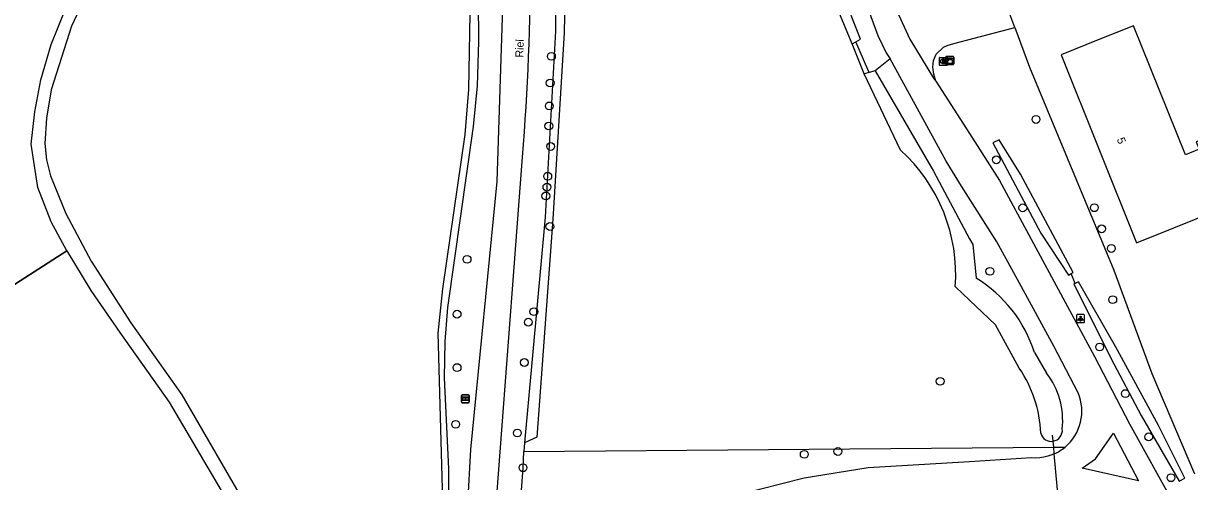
# Model space of a CAD drawing. Extents: x 163863 to 164644, y 379566 to 382155.
# Drawn here: x 164381.7 to 164527.5, y 381338.5 to 381395.8 of the extents above; entities that cross this region are included whole.
import ezdxf

# ---------------------------------------------------------------- set-up
doc = ezdxf.new("R2010")
doc.units = 0
for name, color, linetype in [('IMGEO_Boom', 7, 'Continuous'), ('IMGEO_Bouwland', 7, 'Continuous'), ('IMGEO_Duiker', 7, 'Continuous'), ('IMGEO_Groenvoorziening', 7, 'Continuous'), ('IMGEO_Hek', 7, 'Continuous'), ('IMGEO_Informatiebord', 7, 'Continuous'), ('IMGEO_Kast', 7, 'Continuous'), ('IMGEO_Lichtpunt', 7, 'Continuous'), ('IMGEO_Openbare_ruimte_label', 7, 'Continuous'), ('IMGEO_Pand', 7, 'Continuous'), ('IMGEO_Pand_nummerreeks', 7, 'Continuous'), ('IMGEO_Rijbaan_lokaal_gesloten', 7, 'Continuous'), ('IMGEO_Rijbaan_lokaal_onverhard', 7, 'Continuous'), ('IMGEO_Rioolput', 7, 'Continuous'), ('IMGEO_Waterloop', 7, 'Continuous')]:
    doc.layers.add(name, color=color, linetype=linetype)

msp = doc.modelspace()

# ---------------------------------------------------------------- linework, layer by layer
at = {"layer": 'IMGEO_Boom'}
for centre in [(164447.74, 381391.69), (164447.58, 381388.35), (164447.48, 381385.49), (164508.3, 381383.8), (164447.41, 381382.97), (164447.64, 381380.42), (164503.34, 381378.75), (164447.28, 381376.69), (164447.18, 381375.33), (164447.05, 381374.23), (164506.65, 381372.74), (164515.59, 381372.75), (164447.55, 381370.4), (164516.5, 381370.12), (164517.72, 381367.66), (164437.2, 381366.29), (164502.54, 381364.8), (164517.89, 381361.25), (164435.95, 381359.43), (164445.55, 381359.75), (164444.85, 381358.43), (164516.26, 381355.32), (164444.35, 381353.39), (164435.95, 381352.75), (164496.32, 381351.04), (164519.46, 381349.5), (164435.78, 381345.66), (164443.48, 381344.56), (164522.39, 381344.08), (164479.34, 381341.9), (164483.54, 381342.26), (164444.19, 381340.22), (164525.17, 381338.97)]:
    msp.add_circle(centre, 0.489, dxfattribs=at)
at = {"layer": 'IMGEO_Bouwland'}
msp.add_lwpolyline([(164287.52, 381296.47), (164317.88, 381319.5), (164350.6, 381343.85), (164387.17, 381367.35)], dxfattribs=at)
at = {"layer": 'IMGEO_Duiker'}
for points in [[(164487.45, 381389.67), (164487.29, 381390.03), (164485.77, 381393.51)], [(164513.19, 381363.29), (164512.71, 381364.51)], [(164511.24, 381334.6), (164511.23, 381334.72), (164510.95, 381337.93), (164510.59, 381341.96), (164510.51, 381342.79), (164510.45, 381343.54), (164510.38, 381344.3)]]:
    msp.add_lwpolyline(points, dxfattribs=at)
at = {"layer": 'IMGEO_Groenvoorziening'}
for points in [[(164505.66, 381395.29), (164507.47, 381390.32), (164518.04, 381364.93), (164522.77, 381352.02), (164528.1, 381339.46)], [(164486.82, 381389.49), (164485.33, 381393.26)], [(164490.06, 381391.38), (164488.22, 381389.88)], [(164444.37, 381343.32), (164444.31, 381342.24)], [(164443.5, 381329.17), (164443.79, 381334.56), (164444.19, 381340.22), (164444.31, 381342.24)], [(164444.31, 381342.24), (164510.51, 381342.79), (164511.93, 381342.81)]]:
    msp.add_lwpolyline(points, dxfattribs=at)
at = {"layer": 'IMGEO_Hek'}
msp.add_lwpolyline([(164387.17, 381367.35), (164350.6, 381343.85), (164317.88, 381319.5), (164287.52, 381296.47), (164311.91, 381267.33)], dxfattribs=at)
at = {"layer": 'IMGEO_Informatiebord'}
for p, q in [((164436.49, 381348.45), (164436.49, 381349.25)), ((164436.49, 381349.25), (164436.49, 381348.45)), ((164436.59, 381349.35), (164437.38, 381349.35)), ((164437.38, 381349.35), (164436.59, 381349.35)), ((164437.48, 381349.25), (164437.48, 381348.45)), ((164437.48, 381348.45), (164437.48, 381349.25)), ((164437.38, 381348.35), (164436.59, 381348.35)), ((164436.59, 381348.35), (164437.38, 381348.35))]:
    msp.add_line(p, q, dxfattribs=at)
for points in [[(164436.6, 381349.08), (164437.38, 381349.08), (164437.38, 381348.62), (164436.6, 381348.62), (164436.6, 381349.08)], [(164436.66, 381349.02), (164436.66, 381348.68), (164436.94, 381348.68), (164436.94, 381348.9), (164437.04, 381348.9), (164437.04, 381348.68), (164437.32, 381348.68), (164437.32, 381349.02), (164437.04, 381349.02), (164437.04, 381348.94), (164436.94, 381348.94), (164436.94, 381349.02), (164436.66, 381349.02)]]:
    msp.add_lwpolyline(points, dxfattribs=at)
for centre, start, end in [((164436.59, 381349.25), 90, 180), ((164436.59, 381349.25), 90, 180), ((164437.38, 381349.25), 0, 90), ((164437.38, 381349.25), 360, 90), ((164436.59, 381348.45), 180, 270), ((164436.59, 381348.45), 180, 270), ((164437.38, 381348.45), 270, 0), ((164437.38, 381348.45), 270, 0)]:
    msp.add_arc(centre, 0.1, start, end, dxfattribs=at)
at = {"layer": 'IMGEO_Kast'}
for p, q in [((164497.02, 381390.76), (164497.02, 381391.6)), ((164497.02, 381391.6), (164497.02, 381390.76)), ((164497.1, 381391.68), (164497.94, 381391.68)), ((164497.94, 381391.68), (164497.1, 381391.68)), ((164498.02, 381391.61), (164498.02, 381390.77)), ((164498.02, 381390.77), (164498.02, 381391.61)), ((164497.95, 381390.68), (164497.11, 381390.68)), ((164497.11, 381390.68), (164497.95, 381390.68))]:
    msp.add_line(p, q, dxfattribs=at)
for points in [[(164497.22, 381391.47), (164497.82, 381391.47), (164497.82, 381391.39), (164497.22, 381391.39), (164497.22, 381391.47)], [(164497.22, 381391.3), (164497.82, 381391.3), (164497.82, 381390.81), (164497.22, 381390.81), (164497.22, 381391.3)]]:
    msp.add_lwpolyline(points, dxfattribs=at)
msp.add_circle((164497.3, 381391.14), 0.0377, dxfattribs=at)
for centre, start, end in [((164497.1, 381391.6), 92.4484, 184.2845), ((164497.1, 381391.6), 92.4484, 184.2845), ((164497.94, 381391.6), 2.4484, 94.2845), ((164497.94, 381391.6), 2.4484, 94.2845), ((164497.1, 381390.76), 182.4484, 274.2845), ((164497.1, 381390.76), 182.4484, 274.2845), ((164497.94, 381390.76), 272.4484, 4.2845), ((164497.94, 381390.76), 272.4484, 4.2845)]:
    msp.add_arc(centre, 0.0779, start, end, dxfattribs=at)
at = {"layer": 'IMGEO_Lichtpunt'}
for p, q in [((164513.37, 381359.29), (164513.37, 381358.48)), ((164513.37, 381359.29), (164513.37, 381358.48)), ((164514.27, 381359.39), (164513.46, 381359.39)), ((164514.27, 381359.39), (164513.46, 381359.39)), ((164514.36, 381358.48), (164514.36, 381359.29)), ((164514.36, 381358.48), (164514.36, 381359.29)), ((164513.46, 381358.39), (164514.27, 381358.39)), ((164513.46, 381358.39), (164514.27, 381358.39))]:
    msp.add_line(p, q, dxfattribs=at)
for points in [[(164513.74, 381358.95), (164513.78, 381358.93), (164513.59, 381358.66), (164513.55, 381358.69), (164513.74, 381358.95)], [(164513.84, 381358.91), (164513.89, 381358.91), (164513.89, 381358.58), (164513.84, 381358.58), (164513.84, 381358.91)], [(164513.95, 381358.93), (164513.99, 381358.95), (164514.18, 381358.69), (164514.14, 381358.66), (164513.95, 381358.93)]]:
    msp.add_lwpolyline(points, dxfattribs=at)
msp.add_circle((164513.87, 381359.09), 0.0994, dxfattribs=at)
for centre, start, end in [((164513.46, 381359.29), 90, 180), ((164513.46, 381359.29), 90, 180), ((164514.27, 381359.29), 0, 90), ((164514.27, 381359.29), 0, 90), ((164513.46, 381358.48), 180, 270), ((164513.46, 381358.48), 180, 270), ((164514.27, 381358.48), 270, 0), ((164514.27, 381358.48), 270, 360)]:
    msp.add_arc(centre, 0.0946, start, end, dxfattribs=at)
at = {"layer": 'IMGEO_Pand'}
msp.add_lwpolyline([(164520.5, 381395.51), (164516.07, 381393.74), (164511.43, 381391.87), (164520.86, 381368.36), (164525.51, 381370.22), (164530.92, 381372.39), (164530.81, 381372.66), (164531.54, 381372.95), (164531.69, 381372.56), (164535.63, 381374.14), (164532.25, 381382.56), (164528.32, 381380.98), (164528.68, 381380.07), (164526.97, 381379.39), (164520.5, 381395.51)], dxfattribs=at)
at = {"layer": 'IMGEO_Rijbaan_lokaal_gesloten'}
for points in [[(164442.22, 381457.68), (164442.24, 381448.35), (164442.26, 381444.54), (164442.31, 381432.69), (164442.03, 381410.67), (164440.93, 381376.03), (164437.62, 381342.51), (164436.86, 381328.83), (164436.27, 381323.37), (164435.38, 381319.58), (164433.55, 381313.72), (164431.24, 381307.56), (164428.74, 381302.37)], [(164440.65, 381333.45), (164440.75, 381334.49), (164441.34, 381342.21), (164444.13, 381379.08)]]:
    msp.add_lwpolyline(points, dxfattribs=at)
msp.add_arc((164127.19, 381404.33), 317.95, 355.4455, 359.9916, dxfattribs=at)
at = {"layer": 'IMGEO_Rijbaan_lokaal_onverhard'}
for points in [[(164453.83, 381458.42), (164461.3, 381450.96), (164468.06, 381442.36), (164472.89, 381433.3), (164481.62, 381413.16), (164488.52, 381394.29), (164489.58, 381392.13), (164490.06, 381391.38)], [(164489.95, 381399.53), (164492.54, 381393.86), (164495.51, 381388.98), (164495.77, 381388.57)], [(164505.66, 381395.29), (164504.8, 381397.62)], [(164495.77, 381388.57), (164495.53, 381389.45), (164495.39, 381390.32), (164495.47, 381391.17), (164495.84, 381391.97), (164496.74, 381392.84), (164497.2, 381393.06), (164498.04, 381393.32), (164505.66, 381395.29)], [(164513.55, 381349.6), (164510.53, 381355.42), (164506.25, 381363.3), (164503.41, 381368.49), (164499.01, 381375.46), (164497.08, 381378.56), (164490.06, 381391.38)], [(164495.77, 381388.57), (164500, 381382.04), (164503.75, 381376.16), (164515.61, 381354.14), (164519.97, 381345.71), (164525.51, 381335.7), (164527.86, 381330.74), (164529.04, 381328.58), (164531.51, 381322.61), (164532.72, 381318.95), (164540.2, 381293.84), (164541.11, 381291.26), (164542, 381286.69), (164542.93, 381279.72), (164544.02, 381275.23)], [(164517.97, 381344.54), (164521.12, 381338.58), (164514.08, 381340.16), (164515.72, 381341.34), (164517.97, 381344.54)], [(164510.59, 381341.96), (164510.3, 381341.84), (164509.8, 381341.67), (164509.29, 381341.54), (164508.78, 381341.47), (164508.25, 381341.43), (164507.73, 381341.45), (164500, 381340.97), (164487.33, 381340.19), (164479.32, 381338.91), (164471.46, 381336.92), (164464.88, 381334.66), (164449.43, 381328.52), (164449.13, 381328.41), (164448.56, 381328.25), (164447.99, 381328.15), (164447.4, 381328.1), (164446.81, 381328.1), (164446.23, 381328.15), (164445.65, 381328.25), (164445.09, 381328.41), (164444.54, 381328.61), (164444.01, 381328.87), (164443.5, 381329.17)]]:
    msp.add_lwpolyline(points, dxfattribs=at)
for centre, radius, start, end in [((164508.17, 381347.29), 5.86, 310.0111, 23.194), ((164508.16, 381347.3), 5.87, 294.4431, 310.0184)]:
    msp.add_arc(centre, radius, start, end, dxfattribs=at)
at = {"layer": 'IMGEO_Rioolput'}
for p, q in [((164496.23, 381390.64), (164496.23, 381391.49)), ((164496.3, 381391.56), (164497.16, 381391.56)), ((164497.23, 381391.49), (164497.23, 381390.64)), ((164497.16, 381390.56), (164496.3, 381390.56)), ((164496.74, 381390.78), (164496.71, 381390.78)), ((164496.72, 381391.34), (164496.74, 381391.34))]:
    msp.add_line(p, q, dxfattribs=at)
for points in [[(164496.23, 381390.64), (164496.23, 381391.49)], [(164496.3, 381391.56), (164497.16, 381391.56)], [(164497.23, 381391.49), (164497.23, 381390.64)], [(164497.16, 381390.56), (164496.3, 381390.56)], [(164496.82, 381391.26), (164496.56, 381391.26), (164496.56, 381390.86)], [(164496.56, 381390.86), (164496.69, 381390.86), (164496.69, 381391.02), (164496.7, 381391.02)], [(164496.74, 381391.18), (164496.69, 381391.18), (164496.69, 381391.1)], [(164496.69, 381391.1), (164496.74, 381391.1)], [(164496.75, 381390.99), (164496.82, 381390.86), (164496.96, 381390.86), (164496.89, 381390.99)]]:
    msp.add_lwpolyline(points, dxfattribs=at)
for centre, radius, start, end in [((164496.3, 381391.49), 0.0765, 91.552, 178.448), ((164496.3, 381391.49), 0.0765, 91.552, 178.448), ((164497.15, 381391.49), 0.0765, 1.552, 88.448), ((164497.15, 381391.49), 0.0765, 1.552, 88.448), ((164496.3, 381390.64), 0.0765, 181.552, 268.448), ((164496.3, 381390.64), 0.0765, 181.552, 268.448), ((164496.7, 381390.97), 0.0533, 26.0293, 88.6989), ((164496.75, 381391.08), 0.0964, 77.0061, 93.1865), ((164496.73, 381391.29), 0.19, 274.7715, 282.9687), ((164496.76, 381391.14), 0.0378, 276.6634, 79.6772), ((164496.82, 381391.15), 0.109, 350.3612, 89.416), ((164496.81, 381391.15), 0.112, 277.5842, 350.9817), ((164496.8, 381390.93), 0.108, 29.5134, 73.7905), ((164497.15, 381390.64), 0.0765, 271.552, 358.448), ((164497.15, 381390.64), 0.0765, 271.552, 358.448)]:
    msp.add_arc(centre, radius, start, end, dxfattribs=at)
for centre, major_axis, ratio, start_param, end_param in [((164496.72, 381391.06), (-0.387, 0.002), 0.722429, 4.712389, 7.853982), ((164496.74, 381391.06), (-0.39, 0.002), 0.717154, 1.570796, 4.712389)]:
    msp.add_ellipse(centre, major_axis=major_axis, ratio=ratio, start_param=start_param, end_param=end_param, dxfattribs=at)
at = {"layer": 'IMGEO_Waterloop'}
for points in [[(164448.54, 381452.5), (164447.88, 381447.15), (164447.94, 381444.47), (164448.45, 381420.11), (164448.25, 381394.83), (164446.95, 381371.56), (164444.37, 381343.32)], [(164449.93, 381450.68), (164449.82, 381420.02), (164449.32, 381394.65), (164447.9, 381371.31), (164445.92, 381344.04), (164444.37, 381343.32)], [(164423.74, 381298.57), (164430.45, 381312.12), (164432.38, 381317.5), (164434.01, 381324.36), (164434.72, 381330), (164434.91, 381333.02), (164434.92, 381340.08), (164434.38, 381351.46), (164434.48, 381356.02), (164434.81, 381360.28), (164438.01, 381382.93), (164438.49, 381387.99), (164438.66, 381393.57), (164438.58, 381403.85), (164438.23, 381407.47), (164437.47, 381412.38), (164437.16, 381415.96), (164437.21, 381424.46), (164437.58, 381427.9), (164436.26, 381427.88)], [(164434.19, 381336.08), (164433.57, 381357.04), (164434.19, 381362.6), (164436.96, 381381.93), (164437.41, 381387.54), (164437.63, 381399.41), (164436.95, 381408.32), (164436.41, 381411.28), (164435.98, 381417.22), (164436.15, 381420.7), (164436.03, 381423.26), (164436.26, 381427.88)], [(164485.33, 381393.26), (164477.93, 381411.1), (164472.47, 381424.73)], [(164485.33, 381393.26), (164485.77, 381393.51), (164486.37, 381393.84), (164483.6, 381400.91), (164479.59, 381410.3), (164479.27, 381411.35)], [(164387.17, 381367.35), (164385.24, 381370.99), (164383.54, 381375.27), (164382.71, 381380.71), (164383.19, 381384.77), (164383.93, 381388.75), (164385.23, 381393.19), (164386.96, 381397.52), (164389.07, 381401.5), (164391.05, 381404.79), (164392.18, 381406.36)], [(164389.38, 381398.98), (164387.76, 381395.46), (164385.22, 381387.5), (164384.64, 381383.97), (164384.44, 381380.77), (164384.63, 381378.74), (164385.15, 381376.73), (164387.07, 381372.02), (164390.21, 381366.05), (164395.16, 381358.35), (164401.57, 381349.36), (164411.25, 381332.57)], [(164488.22, 381389.88), (164487.45, 381389.67), (164486.82, 381389.49)], [(164491.37, 381379.95), (164486.82, 381389.49)], [(164488.22, 381389.88), (164495.48, 381377.34), (164500, 381368.88), (164500.39, 381368.15), (164500.84, 381363.93)], [(164512.71, 381364.51), (164512.96, 381364.66), (164506.38, 381376.97), (164503.7, 381381.24), (164502.9, 381380.88), (164508.91, 381369.56), (164512.38, 381364.31), (164512.71, 381364.51)], [(164387.17, 381367.35), (164390.16, 381362.39), (164393.8, 381357.16), (164399.95, 381348.42), (164409.49, 381332.22), (164411.12, 381327.86), (164413.7, 381316.99), (164414.96, 381311.68), (164416.41, 381307.8), (164418.97, 381302.83), (164420.83, 381299.88), (164422.6, 381298.39)], [(164506.21, 381352.67), (164503.23, 381358.09), (164500, 381361.18), (164498.22, 381362.87)], [(164513.19, 381363.29), (164513.02, 381363.21), (164517.64, 381353.91), (164521.46, 381346.77), (164526.21, 381338.53), (164526.91, 381338.9), (164523.62, 381345.49), (164518.23, 381355.39), (164513.62, 381363.49), (164513.19, 381363.29)], [(164508.12, 381354.62), (164509.63, 381352.06)]]:
    msp.add_lwpolyline(points, dxfattribs=at)
for centre, radius, start, end in [((164477.32, 381364.4), 20.95, 355.8205, 47.8876), ((164491.98, 381349.5), 16.93, 17.6325, 58.4553), ((164493.52, 381343.98), 15.38, 2.1274, 34.4033), ((164501.78, 381346.09), 9.86, 353.957, 37.2698), ((164510.22, 381344.9), 1.38, 279.6512, 6.4516), ((164510.22, 381344.89), 1.38, 194.5224, 279.6002)]:
    msp.add_arc(centre, radius, start, end, dxfattribs=at)

# ---------------------------------------------------------------- texts
at = {"layer": 'IMGEO_Openbare_ruimte_label'}
msp.add_text('Riel', height=1, rotation=88.3389, dxfattribs=at).set_placement((164444.22, 381391.52))
at = {"layer": 'IMGEO_Pand_nummerreeks'}
msp.add_text('5', height=1, rotation=291.8639, dxfattribs=at).set_placement((164518.38, 381381.31))

doc.saveas('drawing.dxf')
